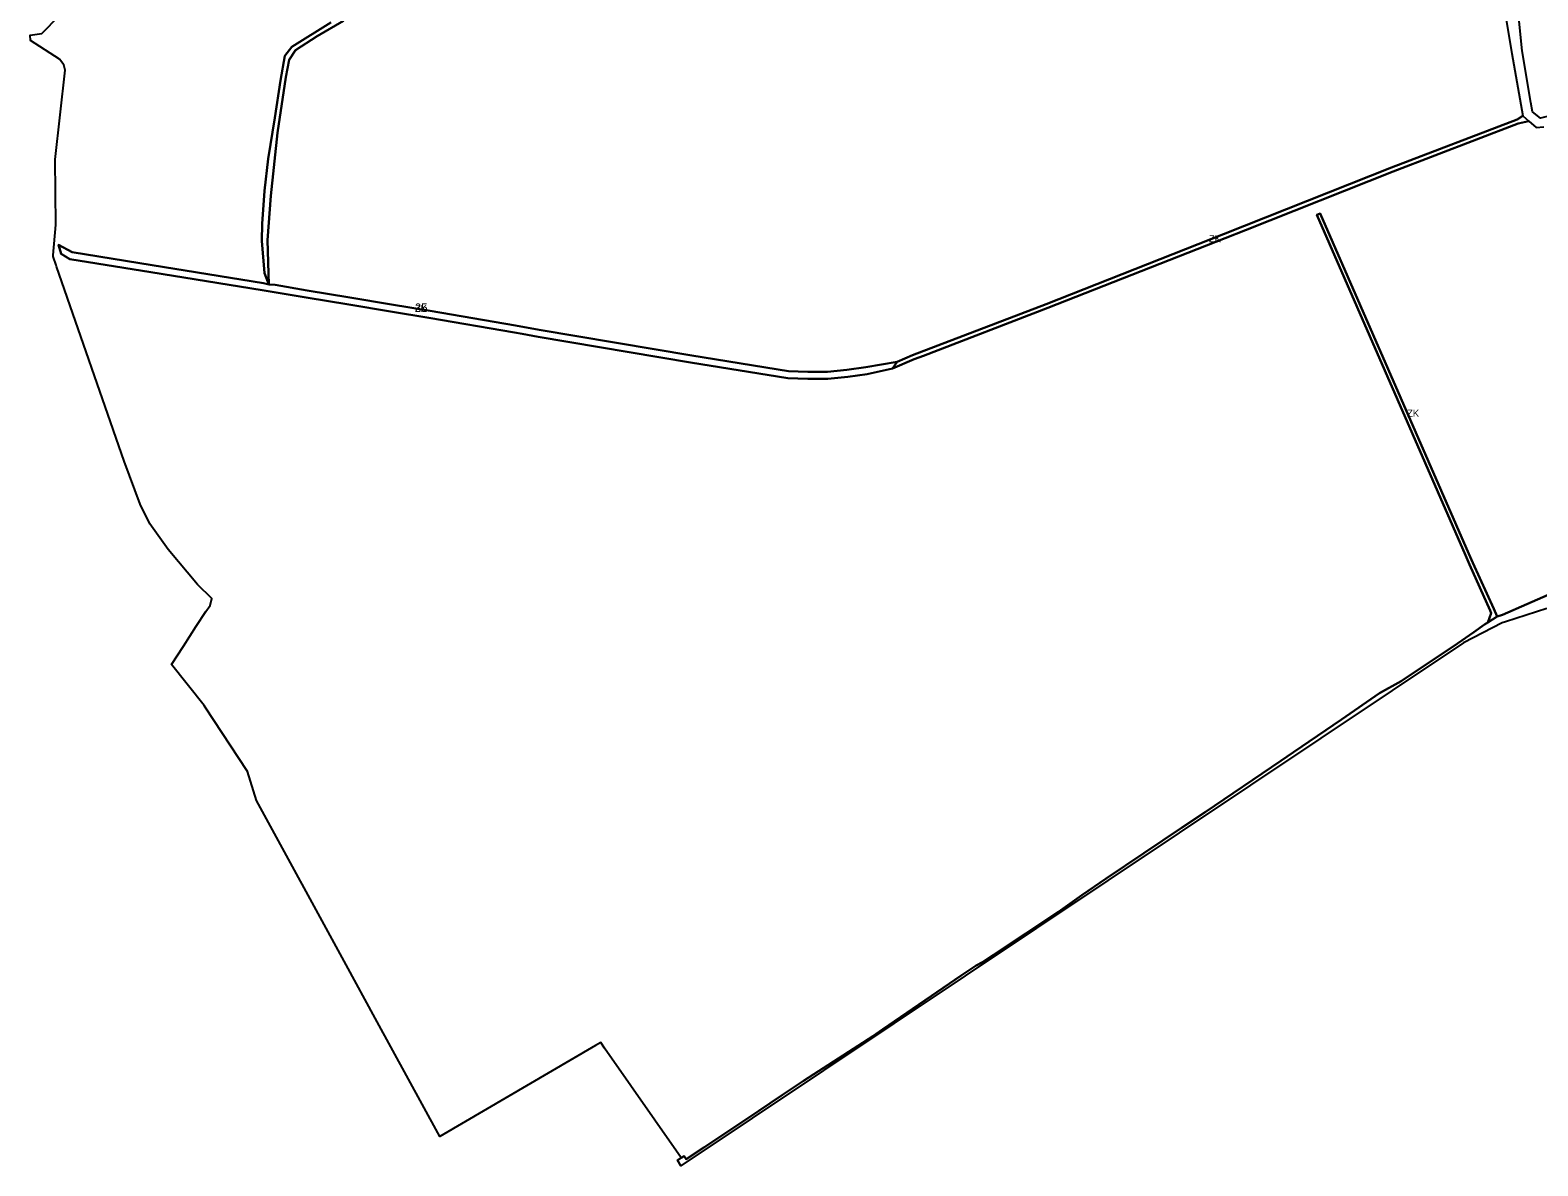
# Model space of a CAD drawing. Extents: x -541351 to -537540, y -1162694 to -1159725.
# Drawn here: x -541351 to -540284, y -1161930 to -1161126 of the extents above; entities that cross this region are included whole.
import ezdxf

# ---------------------------------------------------------------- set-up
doc = ezdxf.new("R2010")
doc.units = 0
for name, color, linetype in [('90640013', 7, 'Continuous'), ('90710013', 7, 'Continuous'), ('90710023', 7, 'Continuous'), ('90750013', 7, 'Continuous'), ('ID_navrh', 7, 'Continuous')]:
    doc.layers.add(name, color=color, linetype=linetype)

msp = doc.modelspace()

# ---------------------------------------------------------------- linework, layer by layer
at = {"layer": '90640013'}
msp.add_lwpolyline([(-540277.11, -1161535.69), (-540306.48, -1161545.1), (-540308.8, -1161545.84), (-540336.16, -1161560.05), (-540890.31, -1161930.15), (-540892.68, -1161926.19), (-540889.95, -1161924.5), (-540887.95, -1161923.26), (-540886.43, -1161925.45), (-540873.99, -1161917.2), (-540843.64, -1161897.07), (-540818.26, -1161879.98), (-540803.39, -1161870.01), (-540754.28, -1161838.41), (-540747.18, -1161833.38), (-540691.67, -1161795.5), (-540681.1, -1161788.46), (-540676.71, -1161786.07), (-540669.18, -1161781.14), (-540622.77, -1161750.26), (-540606.25, -1161738.63), (-540589.03, -1161726.79), (-540535.92, -1161690.81), (-540518.94, -1161679.77), (-540465.44, -1161643.47), (-540456.62, -1161637.24), (-540422.51, -1161614.13), (-540395.65, -1161595.59), (-540380.32, -1161587.03), (-540340.47, -1161560.36), (-540328.77, -1161552.31), (-540321.23, -1161547.02), (-540318.97, -1161545.6), (-540312.32, -1161541.31), (-540308.63, -1161540.09), (-540291.41, -1161532.59), (-540229.38, -1161505.57)], dxfattribs=at)
at = {"layer": '90710013'}
msp.add_lwpolyline([(-541129.064, -1161119.717), (-541147.693, -1161130.687), (-541162.884, -1161140.544), (-541167.448, -1161147.423), (-541169.872, -1161159.489), (-541175.591, -1161198.972), (-541180.464, -1161243.48), (-541182.775, -1161275.083), (-541181.75, -1161306.33), (-541184.81, -1161298.35), (-541186.85, -1161275.44), (-541186.47, -1161263.45), (-541184.87, -1161240.05), (-541182.21, -1161217.36), (-541177.48, -1161188.33), (-541173.66, -1161161.97), (-541170.61, -1161144.41), (-541165.46, -1161138.22), (-541137.93, -1161120.85)], dxfattribs=at)
for points in [[(-540297.43, -1161192.42), (-540386.02, -1161226.29), (-540490.48, -1161267.79), (-540504.91, -1161273.51), (-540630.42, -1161322.96), (-540718.49, -1161356.81), (-540725.06, -1161359.22), (-540740.36, -1161365.79), (-540736.991, -1161361.078), (-540726.169, -1161356.431), (-540631.508, -1161320.164), (-540506.013, -1161270.72), (-540387.109, -1161223.495), (-540298.279, -1161189.533), (-540294.21, -1161187.08), (-540290.019, -1161190.681)], [(-540437.6, -1161256.21), (-540332.4, -1161496.91), (-540329.57, -1161503.37), (-540314.73, -1161536.01), (-540312.32, -1161541.31), (-540318.97, -1161545.6), (-540316.56, -1161539), (-540317.37, -1161537.18), (-540331.84, -1161504.54), (-540334.69, -1161498.02), (-540440, -1161257.07)]]:
    msp.add_lwpolyline(points, close=True, dxfattribs=at)
at = {"layer": '90710023'}
msp.add_lwpolyline([(-540740.36, -1161365.79), (-540758.33, -1161369.77), (-540772.08, -1161371.79), (-540786.11, -1161373.14), (-540800.31, -1161373.2), (-540814.5, -1161372.57), (-540883.34, -1161361.65), (-540991.27, -1161343.31), (-541002.57, -1161341.19), (-541008.05, -1161340.22), (-541068.49, -1161330.02), (-541095.8, -1161325.34), (-541125.26, -1161320.58), (-541155.46, -1161315.61), (-541172.43, -1161312.81), (-541186.56, -1161310.32), (-541265.26, -1161297.71), (-541322.8, -1161288.33), (-541328.76, -1161284.74), (-541330.62, -1161278.35), (-541321.045, -1161283.55), (-541264.462, -1161292.774), (-541185.731, -1161305.389), (-541181.75, -1161306.33), (-541177.3, -1161306.69), (-541154.647, -1161310.677), (-541124.455, -1161315.645), (-541094.979, -1161320.408), (-541067.652, -1161325.091), (-541007.181, -1161335.296), (-540990.398, -1161338.386), (-540882.529, -1161356.716), (-540813.996, -1161367.587), (-540800.21, -1161368.2), (-540786.36, -1161368.141), (-540772.683, -1161366.825), (-540759.235, -1161364.849), (-540736.991, -1161361.078)], close=True, dxfattribs=at)
at = {"layer": '90750013'}
for points in [[(-540316.41, -1161056.82), (-540301.95, -1161142.81), (-540294.21, -1161187.08), (-540298.279, -1161189.533), (-540387.109, -1161223.495), (-540506.013, -1161270.72), (-540631.508, -1161320.164), (-540726.169, -1161356.431), (-540736.991, -1161361.078), (-540759.235, -1161364.849), (-540772.683, -1161366.825), (-540786.36, -1161368.141), (-540800.21, -1161368.2), (-540813.996, -1161367.587), (-540882.529, -1161356.716), (-540990.398, -1161338.386), (-541007.181, -1161335.296), (-541067.652, -1161325.091), (-541094.979, -1161320.408), (-541124.455, -1161315.645), (-541154.647, -1161310.677), (-541177.3, -1161306.69), (-541181.75, -1161306.33), (-541182.775, -1161275.083), (-541180.464, -1161243.48), (-541175.591, -1161198.972), (-541169.872, -1161159.489), (-541167.448, -1161147.423), (-541162.884, -1161140.544), (-541147.693, -1161130.687), (-541129.064, -1161119.717)], [(-540229.38, -1161505.57), (-540291.41, -1161532.59), (-540308.63, -1161540.09), (-540312.32, -1161541.31), (-540314.73, -1161536.01), (-540329.57, -1161503.37), (-540332.4, -1161496.91), (-540437.6, -1161256.21), (-540440, -1161257.07), (-540334.69, -1161498.02), (-540331.84, -1161504.54), (-540317.37, -1161537.18), (-540316.56, -1161539), (-540318.97, -1161545.6), (-540321.23, -1161547.02), (-540328.77, -1161552.31), (-540340.47, -1161560.36), (-540380.32, -1161587.03), (-540395.65, -1161595.59), (-540422.51, -1161614.13), (-540456.62, -1161637.24), (-540465.44, -1161643.47), (-540518.94, -1161679.77), (-540535.92, -1161690.81), (-540589.03, -1161726.79), (-540606.25, -1161738.63), (-540622.77, -1161750.26), (-540669.18, -1161781.14), (-540676.71, -1161786.07), (-540681.1, -1161788.46), (-540691.67, -1161795.5), (-540747.18, -1161833.38), (-540754.28, -1161838.41), (-540803.39, -1161870.01), (-540818.26, -1161879.98), (-540843.64, -1161897.07), (-540873.99, -1161917.2), (-540886.43, -1161925.45), (-540887.95, -1161923.26), (-540889.95, -1161924.5), (-540944.19, -1161846.83), (-540946.92, -1161842.92), (-540950.54, -1161845.03), (-541060.78, -1161909.35), (-541106.46, -1161825.63), (-541127.01, -1161787.97), (-541190.56, -1161671.49), (-541196.86, -1161651.1), (-541226.83, -1161605.4), (-541227.53, -1161604.31), (-541250.72, -1161575.22), (-541242.35, -1161562.34), (-541233.17, -1161548.21), (-541226.45, -1161537.87), (-541223.3, -1161533.47), (-541222.15, -1161528.65), (-541232.32, -1161518.63), (-541253.05, -1161493.9), (-541266.12, -1161475.84), (-541273, -1161461.76), (-541284.15, -1161431.35), (-541332.09, -1161293.63), (-541332.42, -1161292.68), (-541334.6, -1161286.42), (-541334.52, -1161285.55), (-541332.64, -1161264.13), (-541333.01, -1161217.8), (-541326.12, -1161154.72), (-541326.93, -1161150.91), (-541330.08, -1161146.8), (-541350.43, -1161133.7), (-541350.79, -1161129.97), (-541342.47, -1161128.62), (-541293.38, -1161078.37)], [(-540185.73, -1161116.2), (-540176.86, -1161131.88), (-540197.26, -1161143.19), (-540216.93, -1161154.09), (-540211.6, -1161163.37), (-540221.12, -1161167.34), (-540242.426, -1161177.868), (-540246.8, -1161180.03), (-540281.58, -1161188.7), (-540287.3, -1161184.12), (-540288.43, -1161177.55), (-540294.74, -1161140.88), (-540298.48, -1161103.29)], [(-541137.93, -1161120.85), (-541165.46, -1161138.22), (-541170.61, -1161144.41), (-541173.66, -1161161.97), (-541177.48, -1161188.33), (-541182.21, -1161217.36), (-541184.87, -1161240.05), (-541186.47, -1161263.45), (-541186.85, -1161275.44), (-541184.81, -1161298.35), (-541181.75, -1161306.33), (-541185.731, -1161305.389), (-541264.462, -1161292.774), (-541321.045, -1161283.55), (-541330.62, -1161278.35), (-541328.76, -1161284.74), (-541322.8, -1161288.33), (-541265.26, -1161297.71), (-541186.56, -1161310.32), (-541172.43, -1161312.81), (-541155.46, -1161315.61), (-541125.26, -1161320.58), (-541095.8, -1161325.34), (-541068.49, -1161330.02), (-541008.05, -1161340.22), (-541002.57, -1161341.19), (-540991.27, -1161343.31), (-540883.34, -1161361.65), (-540814.5, -1161372.57), (-540800.31, -1161373.2), (-540786.11, -1161373.14), (-540772.08, -1161371.79), (-540758.33, -1161369.77), (-540740.36, -1161365.79), (-540725.06, -1161359.22), (-540718.49, -1161356.81), (-540630.42, -1161322.96), (-540504.91, -1161273.51), (-540490.48, -1161267.79), (-540386.02, -1161226.29), (-540297.43, -1161192.42), (-540290.019, -1161190.681), (-540290.005, -1161190.693), (-540284.83, -1161195.14), (-540279.25, -1161194.73)]]:
    msp.add_lwpolyline(points, dxfattribs=at)

# ---------------------------------------------------------------- texts
at = {"layer": '90710013'}
for p in [(-540516.426, -1161276.435), (-540376.16, -1161399.961)]:
    msp.add_text('ZK', height=5, rotation=0, dxfattribs=at).set_placement(p)
at = {"layer": '90710023'}
msp.add_text('ZK', height=5, rotation=0, dxfattribs=at).set_placement((-541078.43, -1161325.775))
at = {"layer": 'ID_navrh'}
msp.add_text('35', height=6, rotation=0, dxfattribs=at).set_placement((-541078.43, -1161325.775))

doc.saveas('drawing.dxf')
